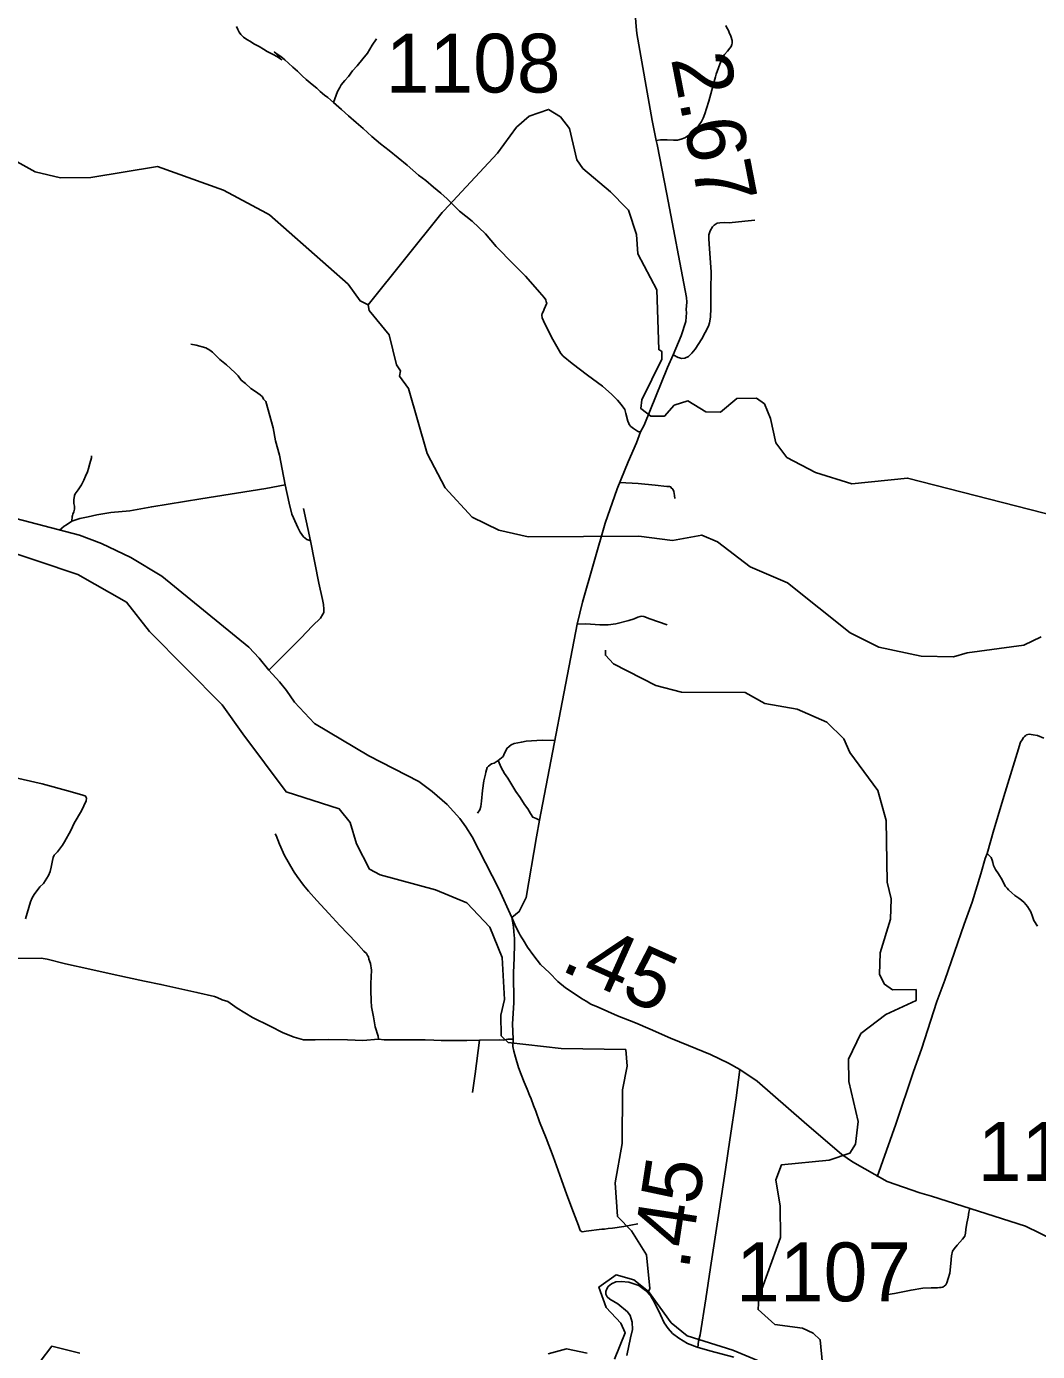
# Model space of a CAD drawing. Extents: x 2290615 to 2522933, y 819489 to 1012715.
# Drawn here: x 2422292 to 2430887, y 857856 to 869123 of the extents above; entities that cross this region are included whole.
import ezdxf

# ---------------------------------------------------------------- set-up
doc = ezdxf.new("R2010")
doc.units = 0
for name, color, linetype in [('Exist Boundary Political CountyLine', 7, 'Continuous'), ('Exist Hydrographic Misc Water Feature', 7, 'Continuous'), ('Exist Road Non-System Type 51', 7, 'Continuous'), ('Exist Road Secondary Mileage Hundredths English Label', 7, 'Continuous'), ('Exist Road Secondary Type 51 Attributed', 7, 'Continuous'), ('Exist Road Secondary Type 51 Number Label', 7, 'Continuous')]:
    doc.layers.add(name, color=color, linetype=linetype)

msp = doc.modelspace()

# ---------------------------------------------------------------- linework, layer by layer
at = {"layer": 'Exist Boundary Political CountyLine'}
msp.add_lwpolyline([(2428305, 857809), (2428100, 857862), (2427994, 857892), (2427911, 857925), (2427837, 857968), (2427785, 858010), (2427747, 858051), (2427714, 858100), (2427681, 858167), (2427631, 858273), (2427599, 858327), (2427554, 858376), (2427498, 858416), (2427413, 858445), (2427347, 858452), (2427302, 858447), (2427265, 858431), (2427238, 858409), (2427225, 858390), (2427218, 858367), (2427218, 858343), (2427228, 858322), (2427252, 858302), (2427320, 858260), (2427401, 858192), (2427423, 858161), (2427441, 858104), (2427443, 858043), (2427428, 857972), (2427395, 857823)], dxfattribs=at)
at = {"layer": 'Exist Hydrographic Misc Water Feature'}
msp.add_line((2425196, 866757), (2425826, 867542), dxfattribs=at)
for points in [[(2424359, 867521), (2424332, 867535), (2423967, 867731), (2423405, 867932), (2422840, 867840), (2422582, 867836), (2422365, 867889), (2422213, 867972), (2421925, 868317), (2421655, 868562), (2421570, 868703), (2421599, 869003), (2421580, 869144), (2421519, 869328), (2421425, 869459), (2421232, 869566), (2421048, 869611)], [(2427409, 867563), (2427393, 867580), (2427258, 867718), (2427022, 867915), (2426971, 867989), (2426909, 868255), (2426832, 868354), (2426731, 868419), (2426566, 868360), (2426459, 868267), (2426295, 868046), (2425841, 867557), (2425826, 867542)], [(2425196, 866757), (2425128, 866791), (2425026, 866931), (2424359, 867521)], [(2431054, 864958), (2429783, 865284), (2429309, 865235), (2428999, 865331), (2428756, 865459), (2428662, 865583), (2428617, 865791), (2428566, 865914), (2428498, 865963), (2428332, 865960), (2428192, 865843), (2428067, 865847), (2427915, 865940), (2427799, 865902), (2427717, 865810), (2427601, 865809), (2427516, 865874), (2427524, 865950), (2427693, 866295), (2427693, 866361), (2427667, 866376), (2427652, 866884), (2427489, 867189), (2427478, 867356), (2427409, 867563)], [(2425196, 866757), (2425204, 866709), (2425374, 866502), (2425436, 866245), (2425470, 866194), (2425463, 866151), (2425539, 866046), (2425697, 865491), (2425852, 865199), (2426080, 864952), (2426307, 864840), (2426557, 864784), (2427499, 864790), (2427783, 864752), (2428032, 864799), (2428166, 864742), (2428444, 864530), (2428763, 864392), (2429294, 863967), (2429537, 863846), (2429897, 863769), (2430172, 863763), (2430288, 863798), (2430770, 863863), (2430919, 863932)], [(2427579, 858367), (2427592, 858392), (2427563, 858677), (2427435, 858882), (2427316, 859005), (2427296, 859290), (2427357, 859624), (2427359, 860080), (2427398, 860282), (2427387, 860423), (2426837, 860433), (2426387, 860484), (2426328, 860540), (2426325, 860717), (2426356, 860850), (2426335, 861207), (2426231, 861465), (2426036, 861671), (2425768, 861781), (2425299, 861910), (2425207, 861958), (2425096, 862174), (2425043, 862355), (2424950, 862470), (2424498, 862616), (2424132, 863109), (2423954, 863355), (2423336, 863980), (2423141, 864228), (2422729, 864464), (2422034, 864695)], [(2429059, 857747), (2429040, 857956), (2428980, 858013), (2428888, 858055), (2428654, 858085), (2428511, 858213), (2428518, 858315), (2428702, 858825), (2428698, 859091), (2428662, 859316), (2428710, 859443), (2429117, 859482), (2429292, 859542), (2429340, 859619), (2429363, 859811), (2429283, 860152), (2429280, 860342), (2429385, 860560), (2429599, 860723), (2429856, 860842), (2429855, 860934), (2429655, 860932), (2429587, 860979), (2429544, 861062), (2429550, 861246), (2429637, 861532), (2429643, 861706), (2429608, 861846), (2429600, 862371), (2429530, 862628), (2429292, 862949), (2429240, 863066), (2429096, 863207), (2428845, 863319), (2428569, 863366), (2428401, 863461), (2427860, 863462), (2427642, 863519), (2427281, 863704), (2427214, 863777), (2427213, 863820)], [(2427290, 857790), (2427381, 858016), (2427346, 858097), (2427219, 858229), (2427158, 858404), (2427305, 858508), (2427454, 858464), (2427579, 858367)], [(2430067, 857219), (2429562, 857482), (2429269, 857475), (2429182, 857503), (2428998, 857694), (2428534, 857768), (2428297, 857866), (2427910, 857989), (2427773, 858099), (2427579, 858367)], [(2422407, 857772), (2422506, 857900), (2422744, 857843)], [(2426726, 857836), (2426882, 857879), (2427059, 857843)]]:
    msp.add_lwpolyline(points, dxfattribs=at)
at = {"layer": 'Exist Road Non-System Type 51'}
msp.add_line((2424707, 864751), (2424647, 865026), dxfattribs=at)
for points in [[(2424077, 869124), (2424088, 869097), (2424100, 869075), (2424114, 869056), (2424137, 869034), (2424164, 869014), (2424195, 868996), (2424225, 868977), (2424271, 868953), (2424307, 868930), (2424339, 868912), (2424390, 868884), (2424419, 868867), (2424462, 868841), (2424400, 868906), (2424431, 868883), (2424455, 868869), (2424487, 868840), (2424520, 868812), (2424556, 868779), (2424595, 868743), (2424635, 868704), (2424670, 868672), (2424720, 868631), (2424761, 868598), (2424789, 868572), (2424824, 868539), (2424854, 868519), (2424902, 868477)], [(2427645, 868154), (2427683, 868161), (2427740, 868159), (2427792, 868157), (2427827, 868156), (2427859, 868165), (2427888, 868176), (2427921, 868197), (2427952, 868219), (2427972, 868238), (2427992, 868259), (2428011, 868287), (2428030, 868317), (2428045, 868345), (2428060, 868382), (2428074, 868425), (2428094, 868488), (2428111, 868551), (2428129, 868626), (2428150, 868695), (2428156, 868719), (2428195, 868827), (2428209, 868856), (2428227, 868885), (2428251, 868914), (2428272, 868939), (2428284, 868954), (2428289, 868971), (2428291, 868982), (2428290, 869004), (2428281, 869042), (2428266, 869073), (2428262, 869081), (2428257, 869094), (2428247, 869113), (2428238, 869131)], [(2425266, 869019), (2425231, 868964), (2425190, 868896), (2425151, 868849), (2425104, 868789), (2425064, 868746), (2425029, 868699), (2424998, 868665), (2424968, 868628), (2424955, 868606), (2424937, 868572), (2424902, 868477)], [(2424902, 868477), (2424969, 868419), (2425030, 868363), (2425095, 868308), (2425154, 868255), (2425227, 868188), (2425301, 868127), (2425374, 868069), (2425451, 868008), (2425528, 867945), (2425625, 867860), (2425686, 867813), (2425753, 867756), (2425815, 867707), (2425868, 867657), (2425909, 867617), (2425974, 867553), (2426081, 867469), (2426195, 867361), (2426284, 867252), (2426432, 867102), (2426534, 866999), (2426615, 866907), (2426653, 866863), (2426694, 866820), (2426706, 866800), (2426711, 866782), (2426715, 866772), (2426705, 866746), (2426694, 866720), (2426686, 866702), (2426676, 866682), (2426674, 866668), (2426675, 866646), (2426699, 866594), (2426767, 866461), (2426823, 866364), (2426835, 866342), (2426855, 866320), (2426932, 866257), (2427062, 866159), (2427189, 866065), (2427268, 865994), (2427317, 865947), (2427347, 865909), (2427380, 865866), (2427388, 865832), (2427405, 865766), (2427412, 865747), (2427416, 865739), (2427430, 865723), (2427452, 865705), (2427485, 865682), (2427497, 865676), (2427513, 865676)], [(2427791, 866330), (2427833, 866309), (2427863, 866301), (2427889, 866303), (2427921, 866316), (2427949, 866346), (2427976, 866379), (2428033, 866467), (2428089, 866574), (2428099, 866604), (2428108, 866653), (2428111, 866727), (2428111, 866888), (2428113, 867035), (2428105, 867156), (2428095, 867272), (2428093, 867320), (2428094, 867352), (2428104, 867386), (2428125, 867421), (2428139, 867433), (2428163, 867451), (2428187, 867455), (2428229, 867456), (2428265, 867455), (2428400, 867467), (2428484, 867476)], [(2424490, 865226), (2424464, 865358), (2424442, 865477), (2424408, 865599), (2424389, 865712), (2424326, 865934), (2424307, 865953), (2424299, 865973), (2424279, 865991), (2424238, 866020), (2424200, 866046), (2424153, 866087), (2424117, 866116), (2424090, 866152), (2424062, 866180), (2423991, 866245), (2423936, 866292), (2423890, 866337), (2423873, 866353), (2423849, 866371), (2423815, 866390), (2423733, 866413), (2423688, 866422)], [(2422844, 865472), (2422843, 865456), (2422830, 865406), (2422818, 865364), (2422809, 865336), (2422793, 865299), (2422778, 865267), (2422758, 865227), (2422731, 865182), (2422705, 865150), (2422699, 865134), (2422696, 865116), (2422694, 865102), (2422694, 865068), (2422699, 865044), (2422699, 865018), (2422697, 865008), (2422693, 864996), (2422686, 864976), (2422682, 864964), (2422680, 864958), (2422677, 864916)], [(2427335, 865245), (2427493, 865236), (2427637, 865224), (2427737, 865211), (2427759, 865212), (2427769, 865210), (2427774, 865200), (2427788, 865188), (2427794, 865170), (2427802, 865136), (2427805, 865110)], [(2424490, 865226), (2424326, 865196), (2423774, 865106), (2423357, 865040), (2423169, 865005), (2423009, 864991), (2422890, 864971), (2422816, 864954), (2422746, 864939), (2422677, 864916)], [(2424707, 864751), (2424691, 864755), (2424676, 864761), (2424660, 864773), (2424648, 864784), (2424618, 864824), (2424599, 864862), (2424587, 864890), (2424547, 864977), (2424526, 865069), (2424490, 865226)], [(2422677, 864916), (2422631, 864887), (2422611, 864875), (2422572, 864840)], [(2424353, 863650), (2424625, 863922), (2424723, 864026), (2424790, 864093), (2424812, 864125), (2424820, 864139), (2424821, 864169), (2424816, 864209), (2424808, 864251), (2424778, 864390), (2424707, 864751)], [(2426973, 864040), (2427046, 864044), (2427165, 864035), (2427238, 864034), (2427302, 864043), (2427412, 864073), (2427458, 864087), (2427489, 864102), (2427508, 864106), (2427521, 864108), (2427539, 864107), (2427590, 864087), (2427740, 864034)], [(2430460, 862092), (2430516, 862291), (2430612, 862613), (2430713, 862945), (2430742, 863037), (2430756, 863057), (2430769, 863077), (2430778, 863086), (2430788, 863095), (2430795, 863100), (2430806, 863103), (2430820, 863105), (2430832, 863104), (2430851, 863100), (2430886, 863093), (2430942, 863073)], [(2426303, 862881), (2426343, 862917), (2426351, 862929), (2426376, 862984), (2426394, 863002), (2426413, 863014), (2426439, 863025), (2426499, 863038), (2426539, 863046), (2426675, 863054), (2426784, 863053)], [(2426126, 862434), (2426146, 862463), (2426155, 862491), (2426161, 862535), (2426169, 862627), (2426180, 862709), (2426193, 862765), (2426197, 862783), (2426203, 862803), (2426208, 862821), (2426220, 862834), (2426244, 862852), (2426268, 862860), (2426303, 862881)], [(2426303, 862881), (2426326, 862821), (2426357, 862772), (2426384, 862732), (2426453, 862619), (2426490, 862568), (2426527, 862508), (2426553, 862470), (2426576, 862431), (2426596, 862401), (2426625, 862388), (2426653, 862374)], [(2422102, 862758), (2422425, 862682), (2422662, 862618), (2422770, 862587), (2422787, 862582), (2422795, 862578), (2422797, 862572), (2422801, 862562), (2422799, 862540), (2422758, 862455), (2422698, 862349), (2422669, 862286), (2422614, 862191), (2422597, 862163), (2422556, 862104), (2422546, 862096), (2422528, 862078), (2422518, 862056), (2422513, 862032), (2422500, 861974), (2422492, 861939), (2422480, 861903), (2422437, 861837), (2422406, 861806), (2422357, 861742), (2422339, 861713), (2422326, 861679), (2422282, 861534)], [(2424405, 862257), (2424415, 862243), (2424444, 862170), (2424486, 862075), (2424504, 862039), (2424539, 861981), (2424568, 861932), (2424594, 861894), (2424647, 861821), (2424690, 861770), (2424759, 861691), (2424861, 861580), (2424956, 861479), (2425094, 861333), (2425161, 861259), (2425182, 861241), (2425192, 861223), (2425198, 861211), (2425202, 861191), (2425217, 861155), (2425224, 861099), (2425219, 860985), (2425218, 860925), (2425221, 860839), (2425224, 860787), (2425243, 860702), (2425257, 860616), (2425282, 860538), (2425284, 860512)], [(2430460, 862092), (2430443, 862049), (2430404, 861917), (2430333, 861676), (2430265, 861490), (2430100, 861015), (2430032, 860831), (2429900, 860427), (2429834, 860238), (2429683, 859789), (2429524, 859340)], [(2430888, 861474), (2430856, 861522), (2430844, 861554), (2430831, 861594), (2430801, 861639), (2430773, 861674), (2430750, 861695), (2430729, 861711), (2430695, 861735), (2430668, 861755), (2430642, 861781), (2430628, 861795), (2430616, 861811), (2430602, 861837), (2430587, 861866), (2430556, 861919), (2430530, 861956), (2430514, 861989), (2430507, 862013), (2430502, 862034), (2430493, 862057), (2430480, 862071), (2430460, 862092)], [(2426418, 861546), (2426433, 861468), (2426436, 861425), (2426440, 861368), (2426442, 861323), (2426437, 861202), (2426432, 861080), (2426434, 860821), (2426425, 860643), (2426429, 860511)], [(2425284, 860512), (2425150, 860502), (2425020, 860507), (2424860, 860508), (2424746, 860507), (2424648, 860507), (2424568, 860530), (2424473, 860567), (2424363, 860623), (2424212, 860697), (2424083, 860775), (2424004, 860832), (2423955, 860847), (2423913, 860866), (2423891, 860876), (2423741, 860910), (2423434, 860977), (2423295, 861005), (2423149, 861037), (2422995, 861069), (2422830, 861107), (2422623, 861154), (2422467, 861193), (2422417, 861200), (2422176, 861198)], [(2426142, 860503), (2426034, 860501), (2425910, 860500), (2425818, 860502), (2425756, 860503), (2425682, 860506), (2425560, 860506), (2425424, 860506), (2425332, 860505), (2425284, 860512)], [(2426083, 860058), (2426106, 860216), (2426142, 860503)], [(2426429, 860511), (2426384, 860511), (2426345, 860504), (2426313, 860506), (2426142, 860503)], [(2427489, 858943), (2427369, 858920), (2427275, 858906), (2427237, 858902), (2427205, 858895), (2427182, 858895), (2427050, 858879), (2427016, 858874), (2427000, 858886), (2426984, 858927), (2426943, 859038), (2426886, 859188), (2426839, 859316), (2426768, 859514), (2426711, 859669), (2426654, 859808), (2426623, 859899), (2426602, 859949), (2426582, 860006), (2426567, 860037), (2426548, 860086), (2426522, 860147), (2426497, 860211), (2426475, 860272), (2426450, 860359), (2426434, 860409), (2426427, 860450), (2426429, 860511)], [(2429579, 858334), (2429670, 858348), (2429813, 858378), (2429913, 858395), (2429983, 858398), (2430015, 858397), (2430036, 858398), (2430054, 858400), (2430069, 858401), (2430080, 858403), (2430089, 858407), (2430094, 858412), (2430107, 858424), (2430116, 858441), (2430128, 858477), (2430141, 858521), (2430150, 858604), (2430156, 858670), (2430165, 858708), (2430180, 858729), (2430203, 858759), (2430228, 858787), (2430250, 858812), (2430268, 858837), (2430276, 858861), (2430279, 858893), (2430286, 858946), (2430298, 858999), (2430304, 859040), (2430313, 859076)]]:
    msp.add_lwpolyline(points, dxfattribs=at)
at = {"layer": 'Exist Road Secondary Type 51 Attributed'}
for points in [[(2427470, 869197), (2427475, 869123), (2427481, 869063), (2427612, 868325), (2427645, 868154), (2427653, 868120), (2427735, 867699), (2427902, 866819), (2427905, 866778), (2427901, 866716), (2427902, 866688), (2427900, 866655), (2427896, 866616), (2427857, 866493), (2427791, 866330), (2427741, 866225), (2427542, 865734), (2427513, 865676), (2427478, 865583), (2427408, 865422), (2427314, 865193), (2427212, 864900), (2427020, 864228), (2426973, 864040), (2426653, 862374), (2426629, 862232), (2426540, 861717), (2426481, 861597), (2426418, 861546)], [(2421592, 865098), (2422741, 864799), (2422928, 864727), (2423179, 864609), (2423442, 864450), (2424183, 863845), (2424269, 863753), (2424353, 863650), (2424444, 863550), (2424503, 863477), (2424571, 863377), (2424740, 863197), (2425203, 862920), (2425626, 862702), (2425741, 862618), (2425867, 862507), (2425975, 862389), (2426028, 862317), (2426081, 862233), (2426307, 861789), (2426418, 861546)], [(2426418, 861546), (2426452, 861466), (2426481, 861413), (2426489, 861397), (2426502, 861373), (2426514, 861356), (2426552, 861295), (2426606, 861220), (2426663, 861148), (2426737, 861075), (2426808, 861002), (2426873, 860949), (2426949, 860899), (2427010, 860859), (2427050, 860835), (2427090, 860810), (2427151, 860783), (2427317, 860709), (2427470, 860652), (2427594, 860596), (2427766, 860520), (2427919, 860458), (2428106, 860381), (2428261, 860307), (2428356, 860253)], [(2428356, 860253), (2428325, 860012), (2428272, 859657), (2428234, 859405), (2428180, 859050), (2428107, 858570), (2428068, 858303), (2428018, 857997), (2428005, 857943), (2428000, 857890)], [(2428356, 860253), (2428503, 860156), (2428903, 859806), (2429224, 859531), (2429313, 859468), (2429610, 859303), (2429887, 859205), (2429985, 859178), (2430784, 858921), (2431034, 858800)]]:
    msp.add_lwpolyline(points, dxfattribs=at)

# ---------------------------------------------------------------- texts
at = {"layer": 'Exist Road Secondary Mileage Hundredths English Label'}
for s, rotation, p in [('2.67', 281.0364, (2427770, 868851)), ('.45', 335.8409, (2426820, 861103)), ('.45', 81.244, (2427920, 858541))]:
    msp.add_text(s, height=500, rotation=rotation, dxfattribs=at).set_placement(p)
at = {"layer": 'Exist Road Secondary Type 51 Number Label'}
for s, p in [('1108', (2425345, 868562)), ('1100', (2430379, 859307)), ('1107', (2428325, 858283))]:
    msp.add_text(s, height=500, rotation=360, dxfattribs=at).set_placement(p)

doc.saveas('drawing.dxf')
